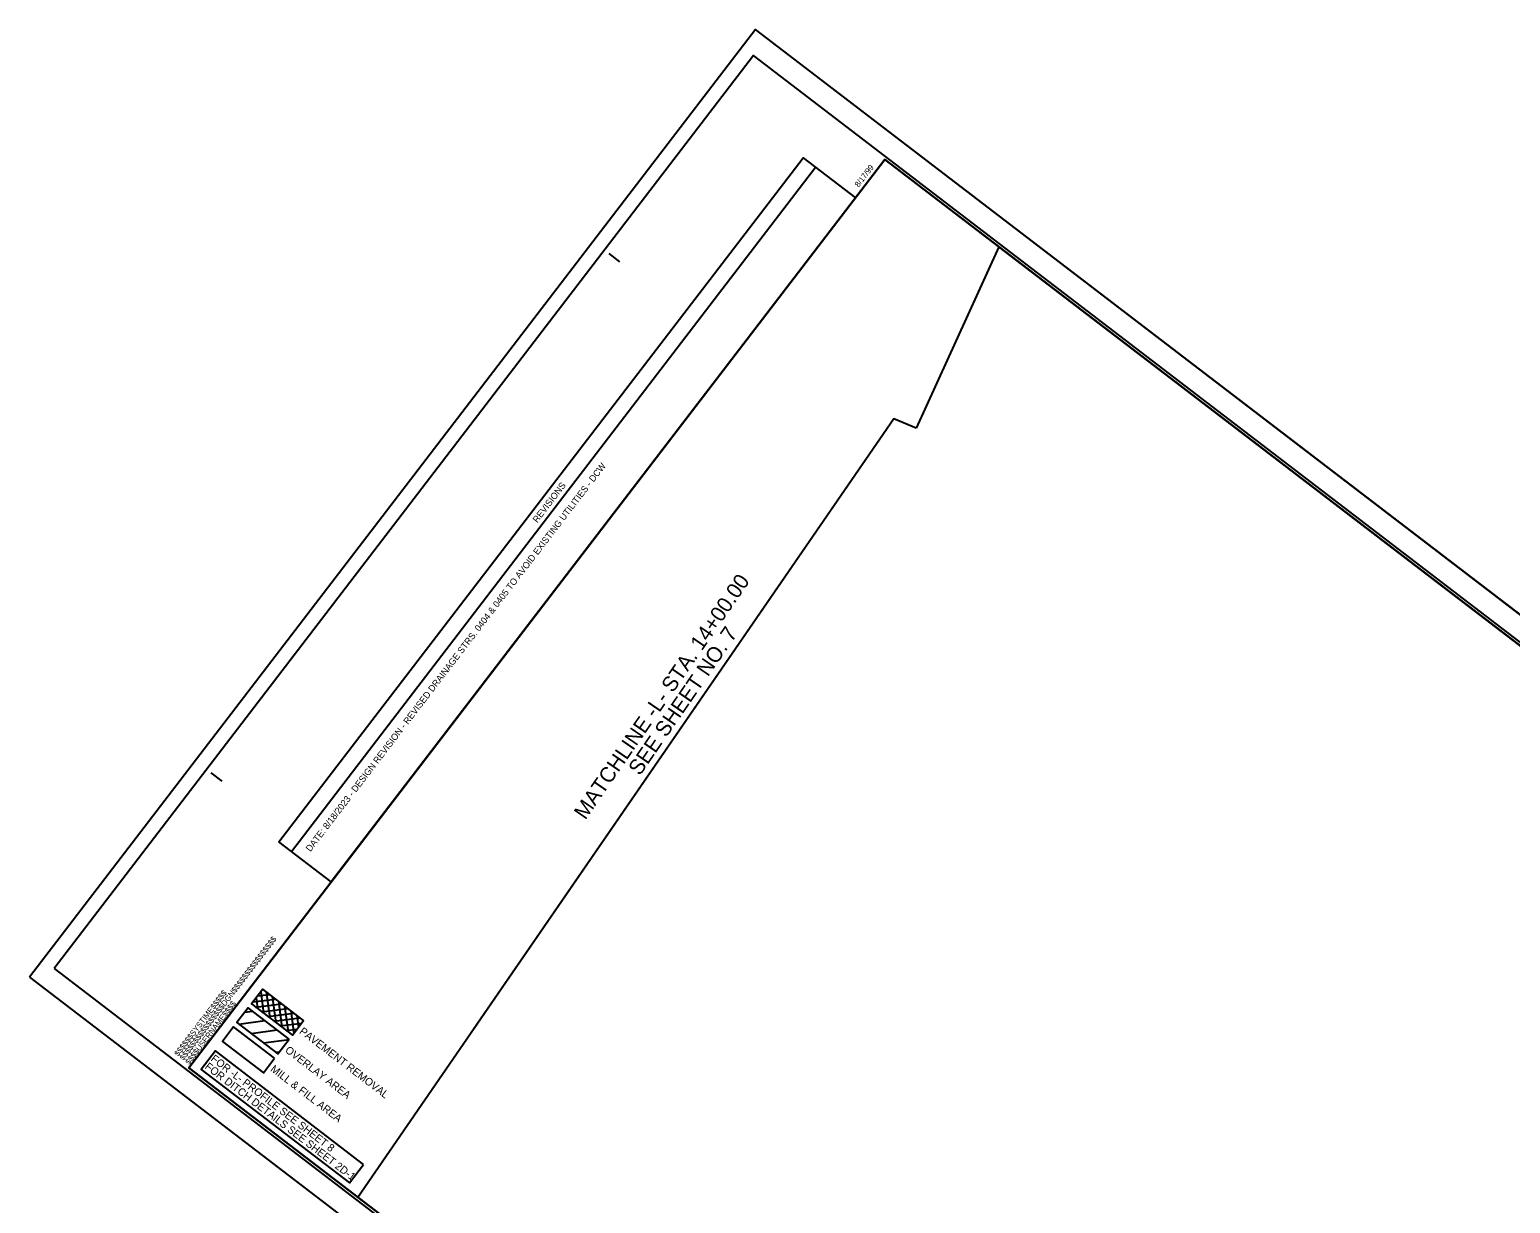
# Model space of a CAD drawing. Extents: x 1617779 to 1619910, y 897617 to 899510.
# Drawn here: x 1617779 to 1619136, y 898433 to 899510 of the extents above; entities that cross this region are included whole.
import ezdxf

# ---------------------------------------------------------------- set-up
doc = ezdxf.new("R2010")
doc.units = 0
for name, color, linetype in [('Matchline', 7, 'Continuous'), ('Matchline Text', 7, 'Continuous'), ('Old_Level_2', 7, 'Continuous'), ('Old_Level_40', 7, 'Continuous'), ('Prop DSN Text', 7, 'Continuous'), ('Prop Rem of Exist Asph Pvmt', 7, 'Continuous'), ('Prop Shade Light', 7, 'Continuous'), ('Sheet Block Revision CELL', 7, 'Continuous'), ('Sheet Cutting Line CELL', 7, 'Continuous'), ('Sheet Layout Plan Border', 7, 'Continuous'), ('Sheet Plan CELL', 7, 'Continuous'), ('Sheet Plot Border Inside CELL', 7, 'Continuous'), ('Sheet Plot Border Outside CELL', 7, 'Continuous')]:
    doc.layers.add(name, color=color, linetype=linetype)

msp = doc.modelspace()

# ---------------------------------------------------------------- linework, layer by layer
at = {"layer": 'Matchline'}
msp.add_line((1618571.1, 899153.2), (1618185.3, 898592.4), dxfattribs=at)
at = {"layer": 'Old_Level_2'}
for p, q in [((1617970.5, 898597.8), (1617994.2, 898601)), ((1617975.9, 898608.7), (1617983, 898609.6)), ((1617981.7, 898589.2), (1618005.4, 898592.4)), ((1617992.9, 898580.7), (1618016.5, 898583.8)), ((1618004.1, 898572.1), (1618007.9, 898572.5))]:
    msp.add_line(p, q, dxfattribs=at)
at = {"layer": 'Old_Level_40'}
for points in [[(1618029.8, 898601), (1617992.3, 898629.8), (1617982, 898616.3), (1618019.5, 898587.5)], [(1618016.5, 898583.9), (1617979, 898612.7), (1617968.7, 898599.2), (1618006.2, 898570.4)], [(1618003.2, 898566.5), (1617965.6, 898595.3), (1617955.3, 898581.8), (1617992.9, 898553)], [(1618084.7, 898469.1), (1617948.9, 898573.2), (1617936, 898556.2), (1618071.8, 898452.2)]]:
    msp.add_lwpolyline(points, close=True, dxfattribs=at)
at = {"layer": 'Prop Rem of Exist Asph Pvmt'}
for p, q in [((1617987.6, 898623.7), (1617998.3, 898625.1)), ((1617990.5, 898627.4), (1617993.1, 898607.8)), ((1617991.9, 898629.3), (1617992.7, 898629.4)), ((1617995.5, 898627.3), (1617998.7, 898603.5)), ((1617983.3, 898618.1), (1618003.9, 898620.8)), ((1617985.8, 898613.4), (1618009.5, 898616.5)), ((1617986.2, 898621.8), (1617987.5, 898612.1)), ((1617991.4, 898609.1), (1618015.1, 898612.2)), ((1618001.1, 898623), (1618004.3, 898599.2)), ((1618006.8, 898618.7), (1618009.9, 898594.9)), ((1618012.4, 898614.4), (1618015.5, 898590.6)), ((1617997, 898604.8), (1618020.8, 898607.9)), ((1618002.6, 898600.5), (1618026.4, 898603.6)), ((1618008.2, 898596.2), (1618028.2, 898598.8)), ((1618018, 898610.1), (1618020.8, 898589.1)), ((1618023.6, 898605.8), (1618025.1, 898594.7)), ((1618029.2, 898601.5), (1618029.4, 898600.4)), ((1618013.8, 898591.9), (1618023.9, 898593.2))]:
    msp.add_line(p, q, dxfattribs=at)
at = {"layer": 'Prop Shade Light'}
msp.add_lwpolyline([(1618003.2, 898566.5), (1617965.6, 898595.3), (1617955.3, 898581.8), (1617992.9, 898553), (1618003.2, 898566.5)], dxfattribs=at)
at = {"layer": 'Sheet Block Revision CELL'}
msp.add_line((1618018.6, 898756.2), (1618499.3, 899383.9), dxfattribs=at)
msp.add_lwpolyline([(1618007.1, 898765), (1618487.8, 899392.7), (1618535.9, 899356), (1618055.1, 898728.2)], close=True, dxfattribs=at)
at = {"layer": 'Sheet Cutting Line CELL'}
for p, q in [((1618444.3, 899510.3), (1617778.5, 898640.9)), ((1619780.9, 898486.7), (1618444.3, 899510.3)), ((1617778.5, 898640.9), (1619115.1, 897617.3))]:
    msp.add_line(p, q, dxfattribs=at)
at = {"layer": 'Sheet Layout Plan Border'}
msp.add_lwpolyline([(1618591.6, 899144.6), (1618571.1, 899153.2), (1618079.6, 898438.7), (1619075.6, 897675.9), (1619235.7, 897874.9), (1619531.9, 898382.6), (1619533.5, 898384.8), (1619467.9, 898435), (1619594.9, 898600.8), (1618667.3, 899311.1)], close=True, dxfattribs=at)
at = {"layer": 'Sheet Plan CELL'}
for p, q in [((1618562.8, 899391.2), (1618562.8, 899391.2)), ((1618309.6, 899304.8), (1618319.6, 899297.2)), ((1617944.8, 898828.4), (1617954.8, 898820.8)), ((1617924.4, 898557.6), (1617924.4, 898557.6))]:
    msp.add_line(p, q, dxfattribs=at)
for points in [[(1619753.7, 898479.1), (1618562.8, 899391.2), (1617924.4, 898557.6), (1619115.3, 897645.5)], [(1617924.4, 898557.6), (1618562.8, 899391.2), (1619594.9, 898600.8), (1619503.7, 898481.6), (1619662.5, 898360), (1619115.3, 897645.5)]]:
    msp.add_lwpolyline(points, close=True, dxfattribs=at)
at = {"layer": 'Sheet Plot Border Inside CELL'}
msp.add_lwpolyline([(1617801, 898648.9), (1619123.7, 897636), (1619765.2, 898473.5), (1618442.5, 899486.5)], close=True, dxfattribs=at)
at = {"layer": 'Sheet Plot Border Outside CELL'}
msp.add_lwpolyline([(1617778.5, 898640.9), (1619115.1, 897617.3), (1619780.9, 898486.7), (1618444.3, 899510.3)], close=True, dxfattribs=at)

# ---------------------------------------------------------------- texts
at = {"layer": 'Matchline Text'}
for s, p in [('MATCHLINE -L- STA. 14+00.00', (1618288.2, 898784.5)), ('SEE SHEET NO. 7', (1618338.1, 898825))]:
    msp.add_text(s, height=14, rotation=55.4794, dxfattribs=at).set_placement(p)
at = {"layer": 'Prop DSN Text'}
for s, p in [('PAVEMENT REMOVAL', (1618025.3, 898589.9)), ('OVERLAY AREA', (1618012.2, 898572.7)), ('FOR DITCH DETAILS SEE SHEET 2D-1', (1617938.6, 898557.6)), ('FOR -L- PROFILE SEE SHEET 8', (1617944.1, 898564.8)), ('MILL & FILL AREA', (1617998.8, 898555.3))]:
    msp.add_text(s, height=7, rotation=322.554, dxfattribs=at).set_placement(p)
at = {"layer": 'Sheet Block Revision CELL'}
for s, p in [('DATE: 8/18/2023 - DESIGN REVISION - REVISED DRAINAGE STRS. 0404 & 0405 TO AVOID EXISTING UTILITIES - DCW', (1618036, 898755.5)), ('REVISIONS', (1618244.1, 899057.3))]:
    msp.add_text(s, height=6, rotation=52.554, dxfattribs=at).set_placement(p)
at = {"layer": 'Sheet Plan CELL'}
for s, p in [('8/17/99', (1618538.8, 899365.2)), ('$$$$$$$$$$$$$$$$DGN$$$$$$$$$$$$$$$$', (1617919.8, 898564.1)), ('$$$$$$SYSTIME$$$$$', (1617914.9, 898567.8)), ('$$$$USERNAME$$$$', (1617925, 898560.1))]:
    msp.add_text(s, height=5.25, rotation=52.554, dxfattribs=at).set_placement(p)

doc.saveas('drawing.dxf')
